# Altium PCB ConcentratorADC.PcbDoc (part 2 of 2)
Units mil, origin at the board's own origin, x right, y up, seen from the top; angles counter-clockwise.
Board outline 14400 x 5650 mil, 4 copper layers (Top Layer, Signal Layer 1, SG, Bottom Layer), stack 25.634 mil thick; 37 components, 129 nets, 1038 pads, 192 vias.
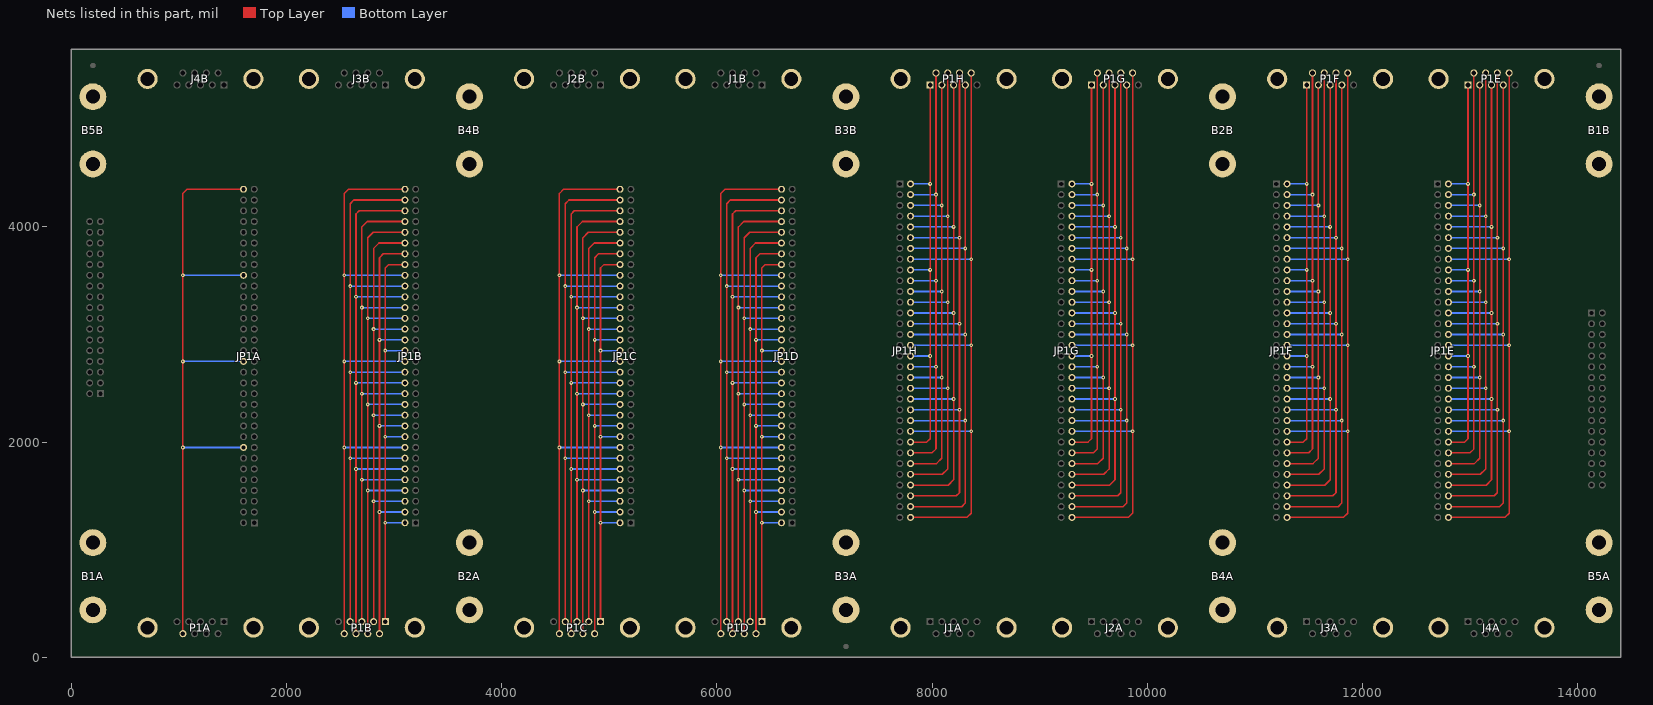
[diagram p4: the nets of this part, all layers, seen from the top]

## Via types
v1: diameter 35, hole 15, Top Layer to Bottom Layer, 192 vias

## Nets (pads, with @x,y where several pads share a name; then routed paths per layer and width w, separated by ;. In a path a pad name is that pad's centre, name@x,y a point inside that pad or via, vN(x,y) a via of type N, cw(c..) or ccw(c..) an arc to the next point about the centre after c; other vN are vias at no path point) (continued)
NetJP1A_16: JP1A.16 JP1A.32 JP1A.48 JP1A.64 P1A.9 | length 6362.6
  Top Layer w15: P1A.9@1036.42,219.09 v1(1036.42,1950) v1(1036.42,2750) v1(1036.42,3550) 1036.42,4311.42 1075,4350 JP1A.64@1600,4350
  Bottom Layer w15: v1(1036.42,1950) JP1A.16@1600,1950 ; v1(1036.42,2750) JP1A.32@1600,2750 ; v1(1036.42,3550) JP1A.48@1600,3550
NetJP1B_2: JP1B.2 JP1B.18 JP1B.34 JP1B.50 P1B.1 | length 4028
  Top Layer w15: P1B.1@2918.11,330.91 v1(2918.11,1250) v1(2918.11,2050) v1(2918.11,2850) 2918.11,3618.11 2950,3650 JP1B.50@3100,3650
  Bottom Layer w15: v1(2918.11,1250) JP1B.2@3100,1250 ; v1(2918.11,2050) JP1B.18@3100,2050 ; v1(2918.11,2850) JP1B.34@3100,2850
NetJP1B_4: JP1B.4 JP1B.20 JP1B.36 JP1B.52 P1B.6 | length 4455.2
  Top Layer w15: P1B.6@2863.58,219.09 v1(2863.58,1350) v1(2863.58,2150) v1(2863.58,2950) 2863.58,3713.58 2900,3750 JP1B.52@3100,3750
  Bottom Layer w15: v1(2863.58,1350) JP1B.4@3100,1350 ; v1(2863.58,2150) JP1B.20@3100,2150 ; v1(2863.58,2950) JP1B.36@3100,2950
NetJP1B_6: JP1B.6 JP1B.22 JP1B.38 JP1B.54 P1B.2 | length 4653.6
  Top Layer w15: P1B.2@2809.06,330.91 v1(2809.06,1450) v1(2809.06,2250) v1(2809.06,3050) 2809.06,3800 2859.06,3850 JP1B.54@3100,3850
  Bottom Layer w15: v1(2809.06,1450) JP1B.6@3100,1450 ; v1(2809.06,2250) JP1B.22@3100,2250 ; v1(2809.06,3050) JP1B.38@3100,3050
NetJP1B_8: JP1B.8 JP1B.24 JP1B.40 JP1B.56 P1B.7 | length 5083.5
  Top Layer w15: P1B.7@2754.53,219.09 v1(2754.53,1550) v1(2754.53,2350) v1(2754.53,3150) 2754.53,3900 2804.53,3950 JP1B.56@3100,3950
  Bottom Layer w15: v1(2754.53,1550) JP1B.8@3100,1550 ; v1(2754.53,2350) JP1B.24@3100,2350 ; v1(2754.53,3150) JP1B.40@3100,3150
NetJP1B_10: JP1B.10 JP1B.26 JP1B.42 JP1B.58 P1B.3 | length 5289.8
  Top Layer w15: P1B.3@2700,330.91 v1(2700,1650) v1(2700,2450) v1(2700,3250) 2700,4000 2750,4050 JP1B.58@3100,4050
  Bottom Layer w15: v1(2700,1650) JP1B.10@3100,1650 ; v1(2700,2450) JP1B.26@3100,2450 ; v1(2700,3250) JP1B.42@3100,3250
NetJP1B_12: JP1B.12 JP1B.28 JP1B.44 JP1B.60 P1B.8 | length 5731.7
  Top Layer w15: P1B.8@2645.47,219.09 v1(2645.47,1750) v1(2645.47,2550) v1(2645.47,3350) 2645.47,4120.47 2675,4150 JP1B.60@3100,4150
  Bottom Layer w15: v1(2645.47,1750) JP1B.12@3100,1750 ; v1(2645.47,2550) JP1B.28@3100,2550 ; v1(2645.47,3350) JP1B.44@3100,3350
NetJP1B_14: JP1B.14 JP1B.30 JP1B.46 JP1B.62 P1B.4 | length 5935.4
  Top Layer w15: P1B.4@2590.94,330.91 v1(2590.94,1850) v1(2590.94,2650) v1(2590.94,3450) 2590.94,4215.94 2625,4250 JP1B.62@3100,4250
  Bottom Layer w15: v1(2590.94,1850) JP1B.14@3100,1850 ; v1(2590.94,2650) JP1B.30@3100,2650 ; v1(2590.94,3450) JP1B.46@3100,3450
NetJP1B_16: JP1B.16 JP1B.32 JP1B.48 JP1B.64 P1B.9 | length 6362.6
  Top Layer w15: P1B.9@2536.42,219.09 v1(2536.42,1950) v1(2536.42,2750) v1(2536.42,3550) 2536.42,4311.42 2575,4350 JP1B.64@3100,4350
  Bottom Layer w15: v1(2536.42,1950) JP1B.16@3100,1950 ; v1(2536.42,2750) JP1B.32@3100,2750 ; v1(2536.42,3550) JP1B.48@3100,3550
NetJP1C_2: JP1C.2 JP1C.18 JP1C.34 JP1C.50 P1C.1 | length 4028
  Top Layer w15: P1C.1@4918.11,330.91 v1(4918.11,1250) v1(4918.11,2050) v1(4918.11,2850) 4918.11,3618.11 4950,3650 JP1C.50@5100,3650
  Bottom Layer w15: v1(4918.11,1250) JP1C.2@5100,1250 ; v1(4918.11,2050) JP1C.18@5100,2050 ; v1(4918.11,2850) JP1C.34@5100,2850
NetJP1C_4: JP1C.4 JP1C.20 JP1C.36 JP1C.52 P1C.6 | length 4455.2
  Top Layer w15: P1C.6@4863.58,219.09 v1(4863.58,1350) v1(4863.58,2150) v1(4863.58,2950) 4863.58,3713.58 4900,3750 JP1C.52@5100,3750
  Bottom Layer w15: v1(4863.58,1350) JP1C.4@5100,1350 ; v1(4863.58,2150) JP1C.20@5100,2150 ; v1(4863.58,2950) JP1C.36@5100,2950
NetJP1C_6: JP1C.6 JP1C.22 JP1C.38 JP1C.54 P1C.2 | length 4653.6
  Top Layer w15: P1C.2@4809.06,330.91 v1(4809.06,1450) v1(4809.06,2250) v1(4809.06,3050) 4809.06,3800 4859.06,3850 JP1C.54@5100,3850
  Bottom Layer w15: v1(4809.06,1450) JP1C.6@5100,1450 ; v1(4809.06,2250) JP1C.22@5100,2250 ; v1(4809.06,3050) JP1C.38@5100,3050
NetJP1C_8: JP1C.8 JP1C.24 JP1C.40 JP1C.56 P1C.7 | length 5083.5
  Top Layer w15: P1C.7@4754.53,219.09 v1(4754.53,1550) v1(4754.53,2350) v1(4754.53,3150) 4754.53,3900 4804.53,3950 JP1C.56@5100,3950
  Bottom Layer w15: v1(4754.53,1550) JP1C.8@5100,1550 ; v1(4754.53,2350) JP1C.24@5100,2350 ; v1(4754.53,3150) JP1C.40@5100,3150
NetJP1C_10: JP1C.10 JP1C.26 JP1C.42 JP1C.58 P1C.3 | length 5289.8
  Top Layer w15: P1C.3@4700,330.91 v1(4700,1650) v1(4700,2450) v1(4700,3250) 4700,4000 4750,4050 JP1C.58@5100,4050
  Bottom Layer w15: v1(4700,1650) JP1C.10@5100,1650 ; v1(4700,2450) JP1C.26@5100,2450 ; v1(4700,3250) JP1C.42@5100,3250
NetJP1C_12: JP1C.12 JP1C.28 JP1C.44 JP1C.60 P1C.8 | length 5731.7
  Top Layer w15: P1C.8@4645.47,219.09 v1(4645.47,1750) v1(4645.47,2550) v1(4645.47,3350) 4645.47,4120.47 4675,4150 JP1C.60@5100,4150
  Bottom Layer w15: v1(4645.47,1750) JP1C.12@5100,1750 ; v1(4645.47,2550) JP1C.28@5100,2550 ; v1(4645.47,3350) JP1C.44@5100,3350
NetJP1C_14: JP1C.14 JP1C.30 JP1C.46 JP1C.62 P1C.4 | length 5935.4
  Top Layer w15: P1C.4@4590.94,330.91 v1(4590.94,1850) v1(4590.94,2650) v1(4590.94,3450) 4590.94,4215.94 4625,4250 JP1C.62@5100,4250
  Bottom Layer w15: v1(4590.94,1850) JP1C.14@5100,1850 ; v1(4590.94,2650) JP1C.30@5100,2650 ; v1(4590.94,3450) JP1C.46@5100,3450
NetJP1C_16: JP1C.16 JP1C.32 JP1C.48 JP1C.64 P1C.9 | length 6362.6
  Top Layer w15: P1C.9@4536.42,219.09 v1(4536.42,1950) v1(4536.42,2750) v1(4536.42,3550) 4536.42,4311.42 4575,4350 JP1C.64@5100,4350
  Bottom Layer w15: v1(4536.42,1950) JP1C.16@5100,1950 ; v1(4536.42,2750) JP1C.32@5100,2750 ; v1(4536.42,3550) JP1C.48@5100,3550
NetJP1D_2: JP1D.2 JP1D.18 JP1D.34 JP1D.50 P1D.1 | length 4028
  Top Layer w15: P1D.1@6418.11,330.91 v1(6418.11,1250) v1(6418.11,2050) v1(6418.11,2850) 6418.11,3618.11 6450,3650 JP1D.50@6600,3650
  Bottom Layer w15: v1(6418.11,1250) JP1D.2@6600,1250 ; v1(6418.11,2050) JP1D.18@6600,2050 ; v1(6418.11,2850) JP1D.34@6600,2850
NetJP1D_4: JP1D.4 JP1D.20 JP1D.36 JP1D.52 P1D.6 | length 4455.2
  Top Layer w15: P1D.6@6363.58,219.09 v1(6363.58,1350) v1(6363.58,2150) v1(6363.58,2950) 6363.58,3713.58 6400,3750 JP1D.52@6600,3750
  Bottom Layer w15: v1(6363.58,1350) JP1D.4@6600,1350 ; v1(6363.58,2150) JP1D.20@6600,2150 ; v1(6363.58,2950) JP1D.36@6600,2950
NetJP1D_6: JP1D.6 JP1D.22 JP1D.38 JP1D.54 P1D.2 | length 4653.6
  Top Layer w15: P1D.2@6309.06,330.91 v1(6309.06,1450) v1(6309.06,2250) v1(6309.06,3050) 6309.06,3800 6359.06,3850 JP1D.54@6600,3850
  Bottom Layer w15: v1(6309.06,1450) JP1D.6@6600,1450 ; v1(6309.06,2250) JP1D.22@6600,2250 ; v1(6309.06,3050) JP1D.38@6600,3050
NetJP1D_8: JP1D.8 JP1D.24 JP1D.40 JP1D.56 P1D.7 | length 5083.5
  Top Layer w15: P1D.7@6254.53,219.09 v1(6254.53,1550) v1(6254.53,2350) v1(6254.53,3150) 6254.53,3900 6304.53,3950 JP1D.56@6600,3950
  Bottom Layer w15: v1(6254.53,1550) JP1D.8@6600,1550 ; v1(6254.53,2350) JP1D.24@6600,2350 ; v1(6254.53,3150) JP1D.40@6600,3150
NetJP1D_10: JP1D.10 JP1D.26 JP1D.42 JP1D.58 P1D.3 | length 5289.8
  Top Layer w15: P1D.3@6200,330.91 v1(6200,1650) v1(6200,2450) v1(6200,3250) 6200,4000 6250,4050 JP1D.58@6600,4050
  Bottom Layer w15: v1(6200,1650) JP1D.10@6600,1650 ; v1(6200,2450) JP1D.26@6600,2450 ; v1(6200,3250) JP1D.42@6600,3250
NetJP1D_12: JP1D.12 JP1D.28 JP1D.44 JP1D.60 P1D.8 | length 5731.7
  Top Layer w15: P1D.8@6145.47,219.09 v1(6145.47,1750) v1(6145.47,2550) v1(6145.47,3350) 6145.47,4120.47 6175,4150 JP1D.60@6600,4150
  Bottom Layer w15: v1(6145.47,1750) JP1D.12@6600,1750 ; v1(6145.47,2550) JP1D.28@6600,2550 ; v1(6145.47,3350) JP1D.44@6600,3350
NetJP1D_14: JP1D.14 JP1D.30 JP1D.46 JP1D.62 P1D.4 | length 5935.4
  Top Layer w15: P1D.4@6090.94,330.91 v1(6090.94,1850) v1(6090.94,2650) v1(6090.94,3450) 6090.94,4215.94 6125,4250 JP1D.62@6600,4250
  Bottom Layer w15: v1(6090.94,1850) JP1D.14@6600,1850 ; v1(6090.94,2650) JP1D.30@6600,2650 ; v1(6090.94,3450) JP1D.46@6600,3450
NetJP1D_16: JP1D.16 JP1D.32 JP1D.48 JP1D.64 P1D.9 | length 6362.6
  Top Layer w15: P1D.9@6036.42,219.09 v1(6036.42,1950) v1(6036.42,2750) v1(6036.42,3550) 6036.42,4311.42 6075,4350 JP1D.64@6600,4350
  Bottom Layer w15: v1(6036.42,1950) JP1D.16@6600,1950 ; v1(6036.42,2750) JP1D.32@6600,2750 ; v1(6036.42,3550) JP1D.48@6600,3550
NetJP1E_2: JP1E.2 JP1E.18 JP1E.34 JP1E.50 P1E.1 | length 4028
  Top Layer w15: JP1E.50@12800,2000 12950,2000 12981.89,2031.89 v1(12981.89,2800) v1(12981.89,3600) v1(12981.89,4400) P1E.1@12981.89,5319.09
  Bottom Layer w15: JP1E.34@12800,2800 v1(12981.89,2800) ; JP1E.18@12800,3600 v1(12981.89,3600) ; JP1E.2@12800,4400 v1(12981.89,4400)
NetJP1E_4: JP1E.4 JP1E.20 JP1E.36 JP1E.52 P1E.6 | length 4455.2
  Top Layer w15: JP1E.52@12800,1900 13000,1900 13036.42,1936.42 v1(13036.42,2700) v1(13036.42,3500) v1(13036.42,4300) P1E.6@13036.42,5430.91
  Bottom Layer w15: JP1E.36@12800,2700 v1(13036.42,2700) ; JP1E.20@12800,3500 v1(13036.42,3500) ; JP1E.4@12800,4300 v1(13036.42,4300)
NetJP1E_6: JP1E.6 JP1E.22 JP1E.38 JP1E.54 P1E.2 | length 4653.6
  Top Layer w15: JP1E.54@12800,1800 13040.94,1800 13090.94,1850 v1(13090.94,2600) v1(13090.94,3400) v1(13090.94,4200) P1E.2@13090.94,5319.09
  Bottom Layer w15: JP1E.38@12800,2600 v1(13090.94,2600) ; JP1E.22@12800,3400 v1(13090.94,3400) ; JP1E.6@12800,4200 v1(13090.94,4200)
NetJP1E_8: JP1E.8 JP1E.24 JP1E.40 JP1E.56 P1E.7 | length 5083.5
  Top Layer w15: JP1E.56@12800,1700 13095.47,1700 13145.47,1750 v1(13145.47,2500) v1(13145.47,3300) v1(13145.47,4100) P1E.7@13145.47,5430.91
  Bottom Layer w15: JP1E.40@12800,2500 v1(13145.47,2500) ; JP1E.24@12800,3300 v1(13145.47,3300) ; JP1E.8@12800,4100 v1(13145.47,4100)
NetJP1E_10: JP1E.10 JP1E.26 JP1E.42 JP1E.58 P1E.3 | length 5289.8
  Top Layer w15: JP1E.58@12800,1600 13150,1600 13200,1650 v1(13200,2400) v1(13200,3200) v1(13200,4000) P1E.3@13200,5319.09
  Bottom Layer w15: JP1E.42@12800,2400 v1(13200,2400) ; JP1E.26@12800,3200 v1(13200,3200) ; JP1E.10@12800,4000 v1(13200,4000)
NetJP1E_12: JP1E.12 JP1E.28 JP1E.44 JP1E.60 P1E.8 | length 5731.7
  Top Layer w15: JP1E.60@12800,1500 13225,1500 13254.53,1529.53 v1(13254.53,2300) v1(13254.53,3100) v1(13254.53,3900) P1E.8@13254.53,5430.91
  Bottom Layer w15: JP1E.44@12800,2300 v1(13254.53,2300) ; JP1E.28@12800,3100 v1(13254.53,3100) ; JP1E.12@12800,3900 v1(13254.53,3900)
NetJP1E_14: JP1E.14 JP1E.30 JP1E.46 JP1E.62 P1E.4 | length 5935.4
  Top Layer w15: JP1E.62@12800,1400 13275,1400 13309.06,1434.06 v1(13309.06,2200) v1(13309.06,3000) v1(13309.06,3800) P1E.4@13309.06,5319.09
  Bottom Layer w15: JP1E.46@12800,2200 v1(13309.06,2200) ; JP1E.30@12800,3000 v1(13309.06,3000) ; JP1E.14@12800,3800 v1(13309.06,3800)
NetJP1E_16: JP1E.16 JP1E.32 JP1E.48 JP1E.64 P1E.9 | length 6362.6
  Top Layer w15: JP1E.64@12800,1300 13325,1300 13363.58,1338.58 v1(13363.58,2100) v1(13363.58,2900) v1(13363.58,3700) P1E.9@13363.58,5430.91
  Bottom Layer w15: JP1E.48@12800,2100 v1(13363.58,2100) ; JP1E.32@12800,2900 v1(13363.58,2900) ; JP1E.16@12800,3700 v1(13363.58,3700)
NetJP1F_2: JP1F.2 JP1F.18 JP1F.34 JP1F.50 P1F.1 | length 4028
  Top Layer w15: JP1F.50@11300,2000 11450,2000 11481.89,2031.89 v1(11481.89,2800) v1(11481.89,3600) v1(11481.89,4400) P1F.1@11481.89,5319.09
  Bottom Layer w15: JP1F.34@11300,2800 v1(11481.89,2800) ; JP1F.18@11300,3600 v1(11481.89,3600) ; JP1F.2@11300,4400 v1(11481.89,4400)
NetJP1F_4: JP1F.4 JP1F.20 JP1F.36 JP1F.52 P1F.6 | length 4455.2
  Top Layer w15: JP1F.52@11300,1900 11500,1900 11536.42,1936.42 v1(11536.42,2700) v1(11536.42,3500) v1(11536.42,4300) P1F.6@11536.42,5430.91
  Bottom Layer w15: JP1F.36@11300,2700 v1(11536.42,2700) ; JP1F.20@11300,3500 v1(11536.42,3500) ; JP1F.4@11300,4300 v1(11536.42,4300)
NetJP1F_6: JP1F.6 JP1F.22 JP1F.38 JP1F.54 P1F.2 | length 4653.6
  Top Layer w15: JP1F.54@11300,1800 11540.94,1800 11590.94,1850 v1(11590.94,2600) v1(11590.94,3400) v1(11590.94,4200) P1F.2@11590.94,5319.09
  Bottom Layer w15: JP1F.38@11300,2600 v1(11590.94,2600) ; JP1F.22@11300,3400 v1(11590.94,3400) ; JP1F.6@11300,4200 v1(11590.94,4200)
NetJP1F_8: JP1F.8 JP1F.24 JP1F.40 JP1F.56 P1F.7 | length 5083.5
  Top Layer w15: JP1F.56@11300,1700 11595.47,1700 11645.47,1750 v1(11645.47,2500) v1(11645.47,3300) v1(11645.47,4100) P1F.7@11645.47,5430.91
  Bottom Layer w15: JP1F.40@11300,2500 v1(11645.47,2500) ; JP1F.24@11300,3300 v1(11645.47,3300) ; JP1F.8@11300,4100 v1(11645.47,4100)
NetJP1F_10: JP1F.10 JP1F.26 JP1F.42 JP1F.58 P1F.3 | length 5289.8
  Top Layer w15: JP1F.58@11300,1600 11650,1600 11700,1650 v1(11700,2400) v1(11700,3200) v1(11700,4000) P1F.3@11700,5319.09
  Bottom Layer w15: JP1F.42@11300,2400 v1(11700,2400) ; JP1F.26@11300,3200 v1(11700,3200) ; JP1F.10@11300,4000 v1(11700,4000)
NetJP1F_12: JP1F.12 JP1F.28 JP1F.44 JP1F.60 P1F.8 | length 5731.7
  Top Layer w15: JP1F.60@11300,1500 11725,1500 11754.53,1529.53 v1(11754.53,2300) v1(11754.53,3100) v1(11754.53,3900) P1F.8@11754.53,5430.91
  Bottom Layer w15: JP1F.44@11300,2300 v1(11754.53,2300) ; JP1F.28@11300,3100 v1(11754.53,3100) ; JP1F.12@11300,3900 v1(11754.53,3900)
NetJP1F_14: JP1F.14 JP1F.30 JP1F.46 JP1F.62 P1F.4 | length 5935.4
  Top Layer w15: JP1F.62@11300,1400 11775,1400 11809.06,1434.06 v1(11809.06,2200) v1(11809.06,3000) v1(11809.06,3800) P1F.4@11809.06,5319.09
  Bottom Layer w15: JP1F.46@11300,2200 v1(11809.06,2200) ; JP1F.30@11300,3000 v1(11809.06,3000) ; JP1F.14@11300,3800 v1(11809.06,3800)
NetJP1F_16: JP1F.16 JP1F.32 JP1F.48 JP1F.64 P1F.9 | length 6362.6
  Top Layer w15: JP1F.64@11300,1300 11825,1300 11863.58,1338.58 v1(11863.58,2100) v1(11863.58,2900) v1(11863.58,3700) P1F.9@11863.58,5430.91
  Bottom Layer w15: JP1F.48@11300,2100 v1(11863.58,2100) ; JP1F.32@11300,2900 v1(11863.58,2900) ; JP1F.16@11300,3700 v1(11863.58,3700)
NetJP1G_2: JP1G.2 JP1G.18 JP1G.34 JP1G.50 P1G.1 | length 4028
  Top Layer w15: JP1G.50@9300,2000 9450,2000 9481.89,2031.89 v1(9481.89,2800) v1(9481.89,3600) v1(9481.89,4400) P1G.1@9481.89,5319.09
  Bottom Layer w15: JP1G.34@9300,2800 v1(9481.89,2800) ; JP1G.18@9300,3600 v1(9481.89,3600) ; JP1G.2@9300,4400 v1(9481.89,4400)
NetJP1G_4: JP1G.4 JP1G.20 JP1G.36 JP1G.52 P1G.6 | length 4455.2
  Top Layer w15: JP1G.52@9300,1900 9500,1900 9536.42,1936.42 v1(9536.42,2700) v1(9536.42,3500) v1(9536.42,4300) P1G.6@9536.42,5430.91
  Bottom Layer w15: JP1G.36@9300,2700 v1(9536.42,2700) ; JP1G.20@9300,3500 v1(9536.42,3500) ; JP1G.4@9300,4300 v1(9536.42,4300)
NetJP1G_6: JP1G.6 JP1G.22 JP1G.38 JP1G.54 P1G.2 | length 4653.6
  Top Layer w15: JP1G.54@9300,1800 9540.94,1800 9590.94,1850 v1(9590.94,2600) v1(9590.94,3400) v1(9590.94,4200) P1G.2@9590.94,5319.09
  Bottom Layer w15: JP1G.38@9300,2600 v1(9590.94,2600) ; JP1G.22@9300,3400 v1(9590.94,3400) ; JP1G.6@9300,4200 v1(9590.94,4200)
NetJP1G_8: JP1G.8 JP1G.24 JP1G.40 JP1G.56 P1G.7 | length 5083.5
  Top Layer w15: JP1G.56@9300,1700 9595.47,1700 9645.47,1750 v1(9645.47,2500) v1(9645.47,3300) v1(9645.47,4100) P1G.7@9645.47,5430.91
  Bottom Layer w15: JP1G.40@9300,2500 v1(9645.47,2500) ; JP1G.24@9300,3300 v1(9645.47,3300) ; JP1G.8@9300,4100 v1(9645.47,4100)
NetJP1G_10: JP1G.10 JP1G.26 JP1G.42 JP1G.58 P1G.3 | length 5289.8
  Top Layer w15: JP1G.58@9300,1600 9650,1600 9700,1650 v1(9700,2400) v1(9700,3200) v1(9700,4000) P1G.3@9700,5319.09
  Bottom Layer w15: JP1G.42@9300,2400 v1(9700,2400) ; JP1G.26@9300,3200 v1(9700,3200) ; JP1G.10@9300,4000 v1(9700,4000)
NetJP1G_12: JP1G.12 JP1G.28 JP1G.44 JP1G.60 P1G.8 | length 5731.7
  Top Layer w15: JP1G.60@9300,1500 9725,1500 9754.53,1529.53 v1(9754.53,2300) v1(9754.53,3100) v1(9754.53,3900) P1G.8@9754.53,5430.91
  Bottom Layer w15: JP1G.44@9300,2300 v1(9754.53,2300) ; JP1G.28@9300,3100 v1(9754.53,3100) ; JP1G.12@9300,3900 v1(9754.53,3900)
NetJP1G_14: JP1G.14 JP1G.30 JP1G.46 JP1G.62 P1G.4 | length 5935.4
  Top Layer w15: JP1G.62@9300,1400 9775,1400 9809.06,1434.06 v1(9809.06,2200) v1(9809.06,3000) v1(9809.06,3800) P1G.4@9809.06,5319.09
  Bottom Layer w15: JP1G.46@9300,2200 v1(9809.06,2200) ; JP1G.30@9300,3000 v1(9809.06,3000) ; JP1G.14@9300,3800 v1(9809.06,3800)
NetJP1G_16: JP1G.16 JP1G.32 JP1G.48 JP1G.64 P1G.9 | length 6362.6
  Top Layer w15: JP1G.64@9300,1300 9825,1300 9863.58,1338.58 v1(9863.58,2100) v1(9863.58,2900) v1(9863.58,3700) P1G.9@9863.58,5430.91
  Bottom Layer w15: JP1G.48@9300,2100 v1(9863.58,2100) ; JP1G.32@9300,2900 v1(9863.58,2900) ; JP1G.16@9300,3700 v1(9863.58,3700)
NetJP1H_2: JP1H.2 JP1H.18 JP1H.34 JP1H.50 P1H.1 | length 4028
  Top Layer w15: JP1H.50@7800,2000 7950,2000 7981.89,2031.89 v1(7981.89,2800) v1(7981.89,3600) v1(7981.89,4400) P1H.1@7981.89,5319.09
  Bottom Layer w15: JP1H.34@7800,2800 v1(7981.89,2800) ; JP1H.18@7800,3600 v1(7981.89,3600) ; JP1H.2@7800,4400 v1(7981.89,4400)
NetJP1H_4: JP1H.4 JP1H.20 JP1H.36 JP1H.52 P1H.6 | length 4455.2
  Top Layer w15: JP1H.52@7800,1900 8000,1900 8036.42,1936.42 v1(8036.42,2700) v1(8036.42,3500) v1(8036.42,4300) P1H.6@8036.42,5430.91
  Bottom Layer w15: JP1H.36@7800,2700 v1(8036.42,2700) ; JP1H.20@7800,3500 v1(8036.42,3500) ; JP1H.4@7800,4300 v1(8036.42,4300)
NetJP1H_6: JP1H.6 JP1H.22 JP1H.38 JP1H.54 P1H.2 | length 4653.6
  Top Layer w15: JP1H.54@7800,1800 8040.94,1800 8090.94,1850 v1(8090.94,2600) v1(8090.94,3400) v1(8090.94,4200) P1H.2@8090.94,5319.09
  Bottom Layer w15: JP1H.38@7800,2600 v1(8090.94,2600) ; JP1H.22@7800,3400 v1(8090.94,3400) ; JP1H.6@7800,4200 v1(8090.94,4200)
NetJP1H_8: JP1H.8 JP1H.24 JP1H.40 JP1H.56 P1H.7 | length 5083.5
  Top Layer w15: JP1H.56@7800,1700 8095.47,1700 8145.47,1750 v1(8145.47,2500) v1(8145.47,3300) v1(8145.47,4100) P1H.7@8145.47,5430.91
  Bottom Layer w15: JP1H.40@7800,2500 v1(8145.47,2500) ; JP1H.24@7800,3300 v1(8145.47,3300) ; JP1H.8@7800,4100 v1(8145.47,4100)
NetJP1H_10: JP1H.10 JP1H.26 JP1H.42 JP1H.58 P1H.3 | length 5289.8
  Top Layer w15: JP1H.58@7800,1600 8150,1600 8200,1650 v1(8200,2400) v1(8200,3200) v1(8200,4000) P1H.3@8200,5319.09
  Bottom Layer w15: JP1H.42@7800,2400 v1(8200,2400) ; JP1H.26@7800,3200 v1(8200,3200) ; JP1H.10@7800,4000 v1(8200,4000)
NetJP1H_12: JP1H.12 JP1H.28 JP1H.44 JP1H.60 P1H.8 | length 5731.7
  Top Layer w15: JP1H.60@7800,1500 8225,1500 8254.53,1529.53 v1(8254.53,2300) v1(8254.53,3100) v1(8254.53,3900) P1H.8@8254.53,5430.91
  Bottom Layer w15: JP1H.44@7800,2300 v1(8254.53,2300) ; JP1H.28@7800,3100 v1(8254.53,3100) ; JP1H.12@7800,3900 v1(8254.53,3900)
NetJP1H_14: JP1H.14 JP1H.30 JP1H.46 JP1H.62 P1H.4 | length 5935.4
  Top Layer w15: JP1H.62@7800,1400 8275,1400 8309.06,1434.06 v1(8309.06,2200) v1(8309.06,3000) v1(8309.06,3800) P1H.4@8309.06,5319.09
  Bottom Layer w15: JP1H.46@7800,2200 v1(8309.06,2200) ; JP1H.30@7800,3000 v1(8309.06,3000) ; JP1H.14@7800,3800 v1(8309.06,3800)
NetJP1H_16: JP1H.16 JP1H.32 JP1H.48 JP1H.64 P1H.9 | length 6362.6
  Top Layer w15: JP1H.64@7800,1300 8325,1300 8363.58,1338.58 v1(8363.58,2100) v1(8363.58,2900) v1(8363.58,3700) P1H.9@8363.58,5430.91
  Bottom Layer w15: JP1H.48@7800,2100 v1(8363.58,2100) ; JP1H.32@7800,2900 v1(8363.58,2900) ; JP1H.16@7800,3700 v1(8363.58,3700)
SGA: B1A.1 B1A.2 B1B.1 B1B.2 B2A.1 B2A.2 B2B.1 B2B.2 B3A.1 B3A.2 B3B.1 B3B.2 B4A.1 B4A.2 B4B.1 B4B.2 B5A.1 B5A.2 B5B.1 B5B.2 J1A.10 J1A.11 J1B.10 J1B.11 J2A.10 J2A.11 J2B.10 J2B.11 J3A.10 J3A.11 J3B.10 J3B.11 J4A.10 J4A.11 J4B.10 J4B.11 P1A.10 P1A.11 P1B.10 P1B.11 P1C.10 P1C.11 P1D.10 P1D.11 P1E.10 P1E.11 P1F.10 P1F.11 P1G.10 P1G.11 P1H.10 P1H.11
pads on no net: J1A.5 J1B.5 J2A.5 J2B.5 J3A.5 J3B.5 J4A.5 J4B.5 P1A.5 P1B.5 P1C.5 P1D.5 P1E.5 P1F.5 P1G.5 P1H.5 S1A.1 S1A.2 S1A.3 S1A.4 S1A.5 S1A.6 S1A.7 S1A.8 S1A.9 S1A.10 S1A.11 S1A.12 S1A.13 S1A.14 S1A.15 S1A.16 S1A.17 S1A.18 S1A.19 S1A.20 S1A.21 S1A.22 S1A.23 S1A.24 S1A.25 S1A.26 S1A.27 S1A.28 S1A.29 S1A.30 S1A.31 S1A.32 S1A.33 S1A.34 S1B.1 S1B.2 S1B.3 S1B.4 S1B.5 S1B.6 S1B.7 S1B.8 S1B.9 S1B.10 S1B.11 S1B.12 S1B.13 S1B.14 S1B.15 S1B.16 S1B.17 S1B.18 S1B.19 S1B.20 S1B.21 S1B.22 S1B.23 S1B.24 S1B.25 S1B.26 S1B.27 S1B.28 S1B.29 S1B.30 S1B.31 S1B.32 S1B.33 S1B.34

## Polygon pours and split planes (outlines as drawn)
SGA on SG (split plane): 14379.9,20.1 20.1,20.1 20.1,5629.9 14379.9,5629.9

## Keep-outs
Keep-Out Layer:
  lines w10: 50,50 14350,50 14350,5600 50,5600 50,50

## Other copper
Top Layer:
  drawing of 512 lines, arcs and shapes, not listed

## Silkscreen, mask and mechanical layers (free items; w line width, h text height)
Top Overlay:
  region: 10450,2625 10450,4500 10181,4500 10181,2625
  text "OUT1" at 1350,4425 h40
  text "OUT2" at 2850,4425 h40
  text "OUT3" at 4850,4425 h40
  text "OUT4" at 6350,4425 h40
  text "IN1-1" at 7600,4420 h40 r180
  text "1" at 7935,4420 h40 r180
  text "IN1-1" at 9100,4420 h40 r180
  text "1" at 9435,4420 h40 r180
  text "IN1-1" at 11100,4420 h40 r180
  text "1" at 11435,4420 h40 r180
  text "IN1-1" at 12600,4420 h40 r180
  text "1" at 12935,4420 h40 r180
  text "9" at 1455,4330 h40
  text "IN4-9" at 1800,4330 h40
  text "9" at 2955,4330 h40
  text "IN4-9" at 3300,4330 h40
  text "9" at 4955,4330 h40
  text "IN4-9" at 5300,4330 h40
  text "9" at 6455,4330 h40
  text "IN4-9" at 6800,4330 h40
  text "IN1-6" at 7600,4320 h40 r180
  text "6" at 7945,4320 h40 r180
  text "IN1-6" at 9100,4320 h40 r180
  text "6" at 9445,4320 h40 r180
  text "IN1-6" at 11100,4320 h40 r180
  text "6" at 11445,4320 h40 r180
  text "IN1-6" at 12600,4320 h40 r180
  text "6" at 12945,4320 h40 r180
  text "4" at 1455,4230 h40
  text "IN4-4" at 1800,4230 h40
  text "4" at 2955,4230 h40
  text "IN4-4" at 3300,4230 h40
  text "4" at 4955,4230 h40
  text "IN4-4" at 5300,4230 h40
  text "4" at 6455,4230 h40
  text "IN4-4" at 6800,4230 h40
  text "IN1-2" at 7600,4220 h40 r180
  text "2" at 7945,4220 h40 r180
  text "IN1-2" at 9100,4220 h40 r180
  text "2" at 9445,4220 h40 r180
  text "IN1-2" at 11100,4220 h40 r180
  text "2" at 11445,4220 h40 r180
  text "IN1-2" at 12600,4220 h40 r180
  text "2" at 12945,4220 h40 r180
  text "Spare Jumpers" at 400,4150 h40 r270
  text "8" at 1455,4130 h40
  text "IN4-8" at 1800,4130 h40
  text "8" at 2955,4130 h40
  text "IN4-8" at 3300,4130 h40
  text "8" at 4955,4130 h40
  text "IN4-8" at 5300,4130 h40
  text "8" at 6455,4130 h40
  text "IN4-8" at 6800,4130 h40
  text "IN1-7" at 7600,4120 h40 r180
  text "7" at 7945,4120 h40 r180
  text "IN1-7" at 9100,4120 h40 r180
  text "7" at 9445,4120 h40 r180
  text "IN1-7" at 11100,4120 h40 r180
  text "7" at 11445,4120 h40 r180
  text "IN1-7" at 12600,4120 h40 r180
  text "7" at 12945,4120 h40 r180
  text "3" at 1455,4030 h40
  text "IN4-3" at 1800,4030 h40
  text "3" at 2955,4030 h40
  text "IN4-3" at 3300,4030 h40
  text "3" at 4955,4030 h40
  text "IN4-3" at 5300,4030 h40
  text "3" at 6455,4030 h40
  text "IN4-3" at 6800,4030 h40
  text "IN1-3" at 7600,4020 h40 r180
  text "3" at 7945,4020 h40 r180
  text "IN1-3" at 9100,4020 h40 r180
  text "3" at 9445,4020 h40 r180
  text "IN1-3" at 11100,4020 h40 r180
  text "3" at 11445,4020 h40 r180
  text "IN1-3" at 12600,4020 h40 r180
  text "3" at 12945,4020 h40 r180
  text "7" at 1455,3930 h40
  text "IN4-7" at 1800,3930 h40
  text "7" at 2955,3930 h40
  text "IN4-7" at 3300,3930 h40
  text "7" at 4955,3930 h40
  text "IN4-7" at 5300,3930 h40
  text "7" at 6455,3930 h40
  text "IN4-7" at 6800,3930 h40
  text "IN1-8" at 7600,3920 h40 r180
  text "8" at 7945,3920 h40 r180
  text "IN1-8" at 9100,3920 h40 r180
  text "8" at 9445,3920 h40 r180
  text "IN1-8" at 11100,3920 h40 r180
  text "8" at 11445,3920 h40 r180
  text "IN1-8" at 12600,3920 h40 r180
  text "8" at 12945,3920 h40 r180
  text "2" at 1455,3830 h40
  text "IN4-2" at 1800,3830 h40
  text "2" at 2955,3830 h40
  text "IN4-2" at 3300,3830 h40
  text "2" at 4955,3830 h40
  text "IN4-2" at 5300,3830 h40
  text "2" at 6455,3830 h40
  text "IN4-2" at 6800,3830 h40
  text "IN1-4" at 7600,3820 h40 r180
  text "4" at 7945,3820 h40 r180
  text "IN1-4" at 9100,3820 h40 r180
  text "4" at 9445,3820 h40 r180
  text "IN1-4" at 11100,3820 h40 r180
  text "4" at 11445,3820 h40 r180
  text "IN1-4" at 12600,3820 h40 r180
  text "4" at 12945,3820 h40 r180
  text "6" at 1455,3730 h40
  text "IN4-6" at 1800,3730 h40
  text "6" at 2955,3730 h40
  text "IN4-6" at 3300,3730 h40
  text "6" at 4955,3730 h40
  text "IN4-6" at 5300,3730 h40
  text "6" at 6455,3730 h40
  text "IN4-6" at 6800,3730 h40
  text "IN1-9" at 7600,3720 h40 r180
  text "9" at 7945,3720 h40 r180
  text "IN1-9" at 9100,3720 h40 r180
  text "9" at 9445,3720 h40 r180
  text "IN1-9" at 11100,3720 h40 r180
  text "9" at 11445,3720 h40 r180
  text "IN1-9" at 12600,3720 h40 r180
  text "9" at 12945,3720 h40 r180
  text "1" at 1465,3630 h40
  text "IN4-1" at 1800,3630 h40
  text "1" at 2965,3630 h40
  text "IN4-1" at 3300,3630 h40
  text "1" at 4965,3630 h40
  text "IN4-1" at 5300,3630 h40
  text "1" at 6465,3630 h40
  text "IN4-1" at 6800,3630 h40
  text "IN2-1" at 7600,3620 h40 r180
  text "1" at 7935,3620 h40 r180
  text "IN2-1" at 9100,3620 h40 r180
  text "1" at 9435,3620 h40 r180
  text "IN2-1" at 11100,3620 h40 r180
  text "1" at 11435,3620 h40 r180
  text "IN2-1" at 12600,3620 h40 r180
  text "1" at 12935,3620 h40 r180
  text "9" at 1455,3530 h40
  text "IN3-9" at 1800,3530 h40
  text "9" at 2955,3530 h40
  text "IN3-9" at 3300,3530 h40
  text "9" at 4955,3530 h40
  text "IN3-9" at 5300,3530 h40
  text "9" at 6455,3530 h40
  text "IN3-9" at 6800,3530 h40
  text "IN2-6" at 7600,3520 h40 r180
  text "6" at 7945,3520 h40 r180
  text "IN2-6" at 9100,3520 h40 r180
  text "6" at 9445,3520 h40 r180
  text "IN2-6" at 11100,3520 h40 r180
  text "6" at 11445,3520 h40 r180
  text "IN2-6" at 12600,3520 h40 r180
  text "6" at 12945,3520 h40 r180
  text "4" at 1455,3430 h40
  text "IN3-4" at 1800,3430 h40
  text "4" at 2955,3430 h40
  text "IN3-4" at 3300,3430 h40
  text "4" at 4955,3430 h40
  text "IN3-4" at 5300,3430 h40
  text "4" at 6455,3430 h40
  text "IN3-4" at 6800,3430 h40
  text "IN2-2" at 7600,3420 h40 r180
  text "2" at 7945,3420 h40 r180
  text "IN2-2" at 9100,3420 h40 r180
  text "2" at 9445,3420 h40 r180
  text "IN2-2" at 11100,3420 h40 r180
  text "2" at 11445,3420 h40 r180
  text "IN2-2" at 12600,3420 h40 r180
  text "2" at 12945,3420 h40 r180
  text "8" at 1455,3330 h40
  text "IN3-8" at 1800,3330 h40
  text "8" at 2955,3330 h40
  text "IN3-8" at 3300,3330 h40
  text "8" at 4955,3330 h40
  text "IN3-8" at 5300,3330 h40
  text "8" at 6455,3330 h40
  text "IN3-8" at 6800,3330 h40
  text "IN2-7" at 7600,3320 h40 r180
  text "7" at 7945,3320 h40 r180
  text "IN2-7" at 9100,3320 h40 r180
  text "7" at 9445,3320 h40 r180
  text "IN2-7" at 11100,3320 h40 r180
  text "7" at 11445,3320 h40 r180
  text "IN2-7" at 12600,3320 h40 r180
  text "7" at 12945,3320 h40 r180
  text "3" at 1455,3230 h40
  text "IN3-3" at 1800,3230 h40
  text "3" at 2955,3230 h40
  text "IN3-3" at 3300,3230 h40
  text "3" at 4955,3230 h40
  text "IN3-3" at 5300,3230 h40
  text "3" at 6455,3230 h40
  text "IN3-3" at 6800,3230 h40
  text "IN2-3" at 7600,3220 h40 r180
  text "3" at 7945,3220 h40 r180
  text "IN2-3" at 9100,3220 h40 r180
  text "3" at 9445,3220 h40 r180
  text "IN2-3" at 11100,3220 h40 r180
  text "3" at 11445,3220 h40 r180
  text "IN2-3" at 12600,3220 h40 r180
  text "3" at 12945,3220 h40 r180
  text "7" at 1455,3130 h40
  text "IN3-7" at 1800,3130 h40
  text "7" at 2955,3130 h40
  text "IN3-7" at 3300,3130 h40
  text "7" at 4955,3130 h40
  text "IN3-7" at 5300,3130 h40
  text "7" at 6455,3130 h40
  text "IN3-7" at 6800,3130 h40
  text "IN2-8" at 7600,3120 h40 r180
  text "8" at 7945,3120 h40 r180
  text "IN2-8" at 9100,3120 h40 r180
  text "8" at 9445,3120 h40 r180
  text "IN2-8" at 11100,3120 h40 r180
  text "8" at 11445,3120 h40 r180
  text "IN2-8" at 12600,3120 h40 r180
  text "8" at 12945,3120 h40 r180
  text "2" at 1455,3030 h40
  text "IN3-2" at 1800,3030 h40
  text "2" at 2955,3030 h40
  text "IN3-2" at 3300,3030 h40
  text "2" at 4955,3030 h40
  text "IN3-2" at 5300,3030 h40
  text "2" at 6455,3030 h40
  text "IN3-2" at 6800,3030 h40
  text "IN2-4" at 7600,3020 h40 r180
  text "4" at 7945,3020 h40 r180
  text "IN2-4" at 9100,3020 h40 r180
  text "4" at 9445,3020 h40 r180
  text "IN2-4" at 11100,3020 h40 r180
  text "4" at 11445,3020 h40 r180
  text "IN2-4" at 12600,3020 h40 r180
  text "4" at 12945,3020 h40 r180
  text "6" at 1455,2930 h40
  text "IN3-6" at 1800,2930 h40
  text "6" at 2955,2930 h40
  text "IN3-6" at 3300,2930 h40
  text "6" at 4955,2930 h40
  text "IN3-6" at 5300,2930 h40
  text "6" at 6455,2930 h40
  text "IN3-6" at 6800,2930 h40
  text "IN2-9" at 7600,2920 h40 r180
  text "9" at 7945,2920 h40 r180
  text "IN2-9" at 9100,2920 h40 r180
  text "9" at 9445,2920 h40 r180
  text "IN2-9" at 11100,2920 h40 r180
  text "9" at 11445,2920 h40 r180
  text "IN2-9" at 12600,2920 h40 r180
  text "9" at 12945,2920 h40 r180
  text "1" at 1465,2830 h40
  text "IN3-1" at 1800,2830 h40
  text "1" at 2965,2830 h40
  text "IN3-1" at 3300,2830 h40
  text "1" at 4965,2830 h40
  text "IN3-1" at 5300,2830 h40
  text "1" at 6465,2830 h40
  text "IN3-1" at 6800,2830 h40
  text "IN3-1" at 7600,2820 h40 r180
  text "1" at 7935,2820 h40 r180
  text "IN3-1" at 9100,2820 h40 r180
  text "1" at 9435,2820 h40 r180
  text "IN3-1" at 11100,2820 h40 r180
  text "1" at 11435,2820 h40 r180
  text "IN3-1" at 12600,2820 h40 r180
  text "1" at 12935,2820 h40 r180
  text "9" at 1455,2730 h40
  text "IN2-9" at 1800,2730 h40
  text "9" at 2955,2730 h40
  text "IN2-9" at 3300,2730 h40
  text "9" at 4955,2730 h40
  text "IN2-9" at 5300,2730 h40
  text "9" at 6455,2730 h40
  text "IN2-9" at 6800,2730 h40
  text "IN3-6" at 7600,2720 h40 r180
  text "6" at 7945,2720 h40 r180
  text "IN3-6" at 9100,2720 h40 r180
  text "6" at 9445,2720 h40 r180
  text "IN3-6" at 11100,2720 h40 r180
  text "6" at 11445,2720 h40 r180
  text "IN3-6" at 12600,2720 h40 r180
  text "6" at 12945,2720 h40 r180
  text "4" at 1455,2630 h40
  text "IN2-4" at 1800,2630 h40
  text "4" at 2955,2630 h40
  text "IN2-4" at 3300,2630 h40
  text "4" at 4955,2630 h40
  text "IN2-4" at 5300,2630 h40
  text "4" at 6455,2630 h40
  text "IN2-4" at 6800,2630 h40
  text "IN3-2" at 7600,2620 h40 r180
  text "2" at 7945,2620 h40 r180
  text "IN3-2" at 9100,2620 h40 r180
  text "2" at 9445,2620 h40 r180
  text "IN3-2" at 11100,2620 h40 r180
  text "2" at 11445,2620 h40 r180
  text "IN3-2" at 12600,2620 h40 r180
  text "2" at 12945,2620 h40 r180
  text "8" at 1455,2530 h40
  text "IN2-8" at 1800,2530 h40
  text "8" at 2955,2530 h40
  text "IN2-8" at 3300,2530 h40
  text "8" at 4955,2530 h40
  text "IN2-8" at 5300,2530 h40
  text "8" at 6455,2530 h40
  text "IN2-8" at 6800,2530 h40
  text "IN3-7" at 7600,2520 h40 r180
  text "7" at 7945,2520 h40 r180
  text "IN3-7" at 9100,2520 h40 r180
  text "7" at 9445,2520 h40 r180
  text "IN3-7" at 11100,2520 h40 r180
  text "7" at 11445,2520 h40 r180
  text "IN3-7" at 12600,2520 h40 r180
  text "7" at 12945,2520 h40 r180
  text "3" at 1455,2430 h40
  text "IN2-3" at 1800,2430 h40
  text "3" at 2955,2430 h40
  text "IN2-3" at 3300,2430 h40
  text "3" at 4955,2430 h40
  text "IN2-3" at 5300,2430 h40
  text "3" at 6455,2430 h40
  text "IN2-3" at 6800,2430 h40
  text "IN3-3" at 7600,2420 h40 r180
  text "3" at 7945,2420 h40 r180
  text "IN3-3" at 9100,2420 h40 r180
  text "3" at 9445,2420 h40 r180
  text "IN3-3" at 11100,2420 h40 r180
  text "3" at 11445,2420 h40 r180
  text "IN3-3" at 12600,2420 h40 r180
  text "3" at 12945,2420 h40 r180
  text "7" at 1455,2330 h40
  text "IN2-7" at 1800,2330 h40
  text "7" at 2955,2330 h40
  text "IN2-7" at 3300,2330 h40
  text "7" at 4955,2330 h40
  text "IN2-7" at 5300,2330 h40
  text "7" at 6455,2330 h40
  text "IN2-7" at 6800,2330 h40
  text "IN3-8" at 7600,2320 h40 r180
  text "8" at 7945,2320 h40 r180
  text "IN3-8" at 9100,2320 h40 r180
  text "8" at 9445,2320 h40 r180
  text "IN3-8" at 11100,2320 h40 r180
  text "8" at 11445,2320 h40 r180
  text "IN3-8" at 12600,2320 h40 r180
  text "8" at 12945,2320 h40 r180
  text "2" at 1455,2230 h40
  text "IN2-2" at 1800,2230 h40
  text "2" at 2955,2230 h40
  text "IN2-2" at 3300,2230 h40
  text "2" at 4955,2230 h40
  text "IN2-2" at 5300,2230 h40
  text "2" at 6455,2230 h40
  text "IN2-2" at 6800,2230 h40
  text "IN3-4" at 7600,2220 h40 r180
  text "4" at 7945,2220 h40 r180
  text "IN3-4" at 9100,2220 h40 r180
  text "4" at 9445,2220 h40 r180
  text "IN3-4" at 11100,2220 h40 r180
  text "4" at 11445,2220 h40 r180
  text "IN3-4" at 12600,2220 h40 r180
  text "4" at 12945,2220 h40 r180
  text "6" at 1455,2130 h40
  text "IN2-6" at 1800,2130 h40
  text "6" at 2955,2130 h40
  text "IN2-6" at 3300,2130 h40
  text "6" at 4955,2130 h40
  text "IN2-6" at 5300,2130 h40
  text "6" at 6455,2130 h40
  text "IN2-6" at 6800,2130 h40
  text "IN3-9" at 7600,2120 h40 r180
  text "9" at 7945,2120 h40 r180
  text "IN3-9" at 9100,2120 h40 r180
  text "9" at 9445,2120 h40 r180
  text "IN3-9" at 11100,2120 h40 r180
  text "9" at 11445,2120 h40 r180
  text "IN3-9" at 12600,2120 h40 r180
  text "9" at 12945,2120 h40 r180
  text "1" at 1465,2030 h40
  text "IN2-1" at 1800,2030 h40
  text "1" at 2965,2030 h40
  text "IN2-1" at 3300,2030 h40
  text "1" at 4965,2030 h40
  text "IN2-1" at 5300,2030 h40
  text "1" at 6465,2030 h40
  text "IN2-1" at 6800,2030 h40
  text "IN4-1" at 7600,2020 h40 r180
  text "1" at 7935,2020 h40 r180
  text "IN4-1" at 9100,2020 h40 r180
  text "1" at 9435,2020 h40 r180
  text "IN4-1" at 11100,2020 h40 r180
  text "1" at 11435,2020 h40 r180
  text "IN4-1" at 12600,2020 h40 r180
  text "1" at 12935,2020 h40 r180
  text "9" at 1455,1930 h40
  text "IN1-9" at 1800,1930 h40
  text "9" at 2955,1930 h40
  text "IN1-9" at 3300,1930 h40
  text "9" at 4955,1930 h40
  text "IN1-9" at 5300,1930 h40
  text "9" at 6455,1930 h40
  text "IN1-9" at 6800,1930 h40
  text "IN4-6" at 7600,1920 h40 r180
  text "6" at 7945,1920 h40 r180
  text "IN4-6" at 9100,1920 h40 r180
  text "6" at 9445,1920 h40 r180
  text "IN4-6" at 11100,1920 h40 r180
  text "6" at 11445,1920 h40 r180
  text "IN4-6" at 12600,1920 h40 r180
  text "6" at 12945,1920 h40 r180
  text "4" at 1455,1830 h40
  text "IN1-4" at 1800,1830 h40
  text "4" at 2955,1830 h40
  text "IN1-4" at 3300,1830 h40
  text "4" at 4955,1830 h40
  text "IN1-4" at 5300,1830 h40
  text "4" at 6455,1830 h40
  text "IN1-4" at 6800,1830 h40
  text "IN4-2" at 7600,1820 h40 r180
  text "2" at 7945,1820 h40 r180
  text "IN4-2" at 9100,1820 h40 r180
  text "2" at 9445,1820 h40 r180
  text "IN4-2" at 11100,1820 h40 r180
  text "2" at 11445,1820 h40 r180
  text "IN4-2" at 12600,1820 h40 r180
  text "2" at 12945,1820 h40 r180
  text "8" at 1455,1730 h40
  text "IN1-8" at 1800,1730 h40
  text "8" at 2955,1730 h40
  text "IN1-8" at 3300,1730 h40
  text "8" at 4955,1730 h40
  text "IN1-8" at 5300,1730 h40
  text "8" at 6455,1730 h40
  text "IN1-8" at 6800,1730 h40
  text "Slow Controls Concentrator ADC" at 10125,1725 h200 r90
  text "D1700379" at 10325,1725 h180 r90
  text "IN4-7" at 7600,1720 h40 r180
  text "7" at 7945,1720 h40 r180
  text "IN4-7" at 9100,1720 h40 r180
  text "7" at 9445,1720 h40 r180
  text "IN4-7" at 11100,1720 h40 r180
  text "7" at 11445,1720 h40 r180
  text "IN4-7" at 12600,1720 h40 r180
  text "7" at 12945,1720 h40 r180
  text "3" at 1455,1630 h40
  text "IN1-3" at 1800,1630 h40
  text "3" at 2955,1630 h40
  text "IN1-3" at 3300,1630 h40
  text "3" at 4955,1630 h40
  text "IN1-3" at 5300,1630 h40
  text "3" at 6455,1630 h40
  text "IN1-3" at 6800,1630 h40
  text "IN4-3" at 7600,1620 h40 r180
  text "3" at 7945,1620 h40 r180
  text "IN4-3" at 9100,1620 h40 r180
  text "3" at 9445,1620 h40 r180
  text "IN4-3" at 11100,1620 h40 r180
  text "3" at 11445,1620 h40 r180
  text "IN4-3" at 12600,1620 h40 r180
  text "3" at 12945,1620 h40 r180
  text "7" at 1455,1530 h40
  text "IN1-7" at 1800,1530 h40
  text "7" at 2955,1530 h40
  text "IN1-7" at 3300,1530 h40
  text "7" at 4955,1530 h40
  text "IN1-7" at 5300,1530 h40
  text "7" at 6455,1530 h40
  text "IN1-7" at 6800,1530 h40
  text "IN4-8" at 7600,1520 h40 r180
  text "8" at 7945,1520 h40 r180
  text "IN4-8" at 9100,1520 h40 r180
  text "8" at 9445,1520 h40 r180
  text "IN4-8" at 11100,1520 h40 r180
  text "8" at 11445,1520 h40 r180
  text "IN4-8" at 12600,1520 h40 r180
  text "8" at 12945,1520 h40 r180
  text "Spare Jumpers" at 14000,1500 h40 r90
  text "2" at 1455,1430 h40
  text "IN1-2" at 1800,1430 h40
  text "2" at 2955,1430 h40
  text "IN1-2" at 3300,1430 h40
  text "2" at 4955,1430 h40
  text "IN1-2" at 5300,1430 h40
  text "2" at 6455,1430 h40
  text "IN1-2" at 6800,1430 h40
  text "IN4-4" at 7600,1420 h40 r180
  text "4" at 7945,1420 h40 r180
  text "IN4-4" at 9100,1420 h40 r180
  text "4" at 9445,1420 h40 r180
  text "IN4-4" at 11100,1420 h40 r180
  text "4" at 11445,1420 h40 r180
  text "IN4-4" at 12600,1420 h40 r180
  text "4" at 12945,1420 h40 r180
  text "6" at 1455,1330 h40
  text "IN1-6" at 1800,1330 h40
  text "6" at 2955,1330 h40
  text "IN1-6" at 3300,1330 h40
  text "6" at 4955,1330 h40
  text "IN1-6" at 5300,1330 h40
  text "6" at 6455,1330 h40
  text "IN1-6" at 6800,1330 h40
  text "IN4-9" at 7600,1320 h40 r180
  text "9" at 7945,1320 h40 r180
  text "IN4-9" at 9100,1320 h40 r180
  text "9" at 9445,1320 h40 r180
  text "IN4-9" at 11100,1320 h40 r180
  text "9" at 11445,1320 h40 r180
  text "IN4-9" at 12600,1320 h40 r180
  text "9" at 12945,1320 h40 r180
  text "1" at 1465,1230 h40
  text "IN1-1" at 1800,1230 h40
  text "1" at 2965,1230 h40
  text "IN1-1" at 3300,1230 h40
  text "1" at 4965,1230 h40
  text "IN1-1" at 5300,1230 h40
  text "1" at 6465,1230 h40
  text "IN1-1" at 6800,1230 h40
  text "OUT4" at 8050,1225 h40 r180
  text "OUT3" at 9550,1225 h40 r180
  text "OUT2" at 11550,1225 h40 r180
  text "OUT1" at 13050,1225 h40 r180
Mechanical 1:
  the board outline again, w10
